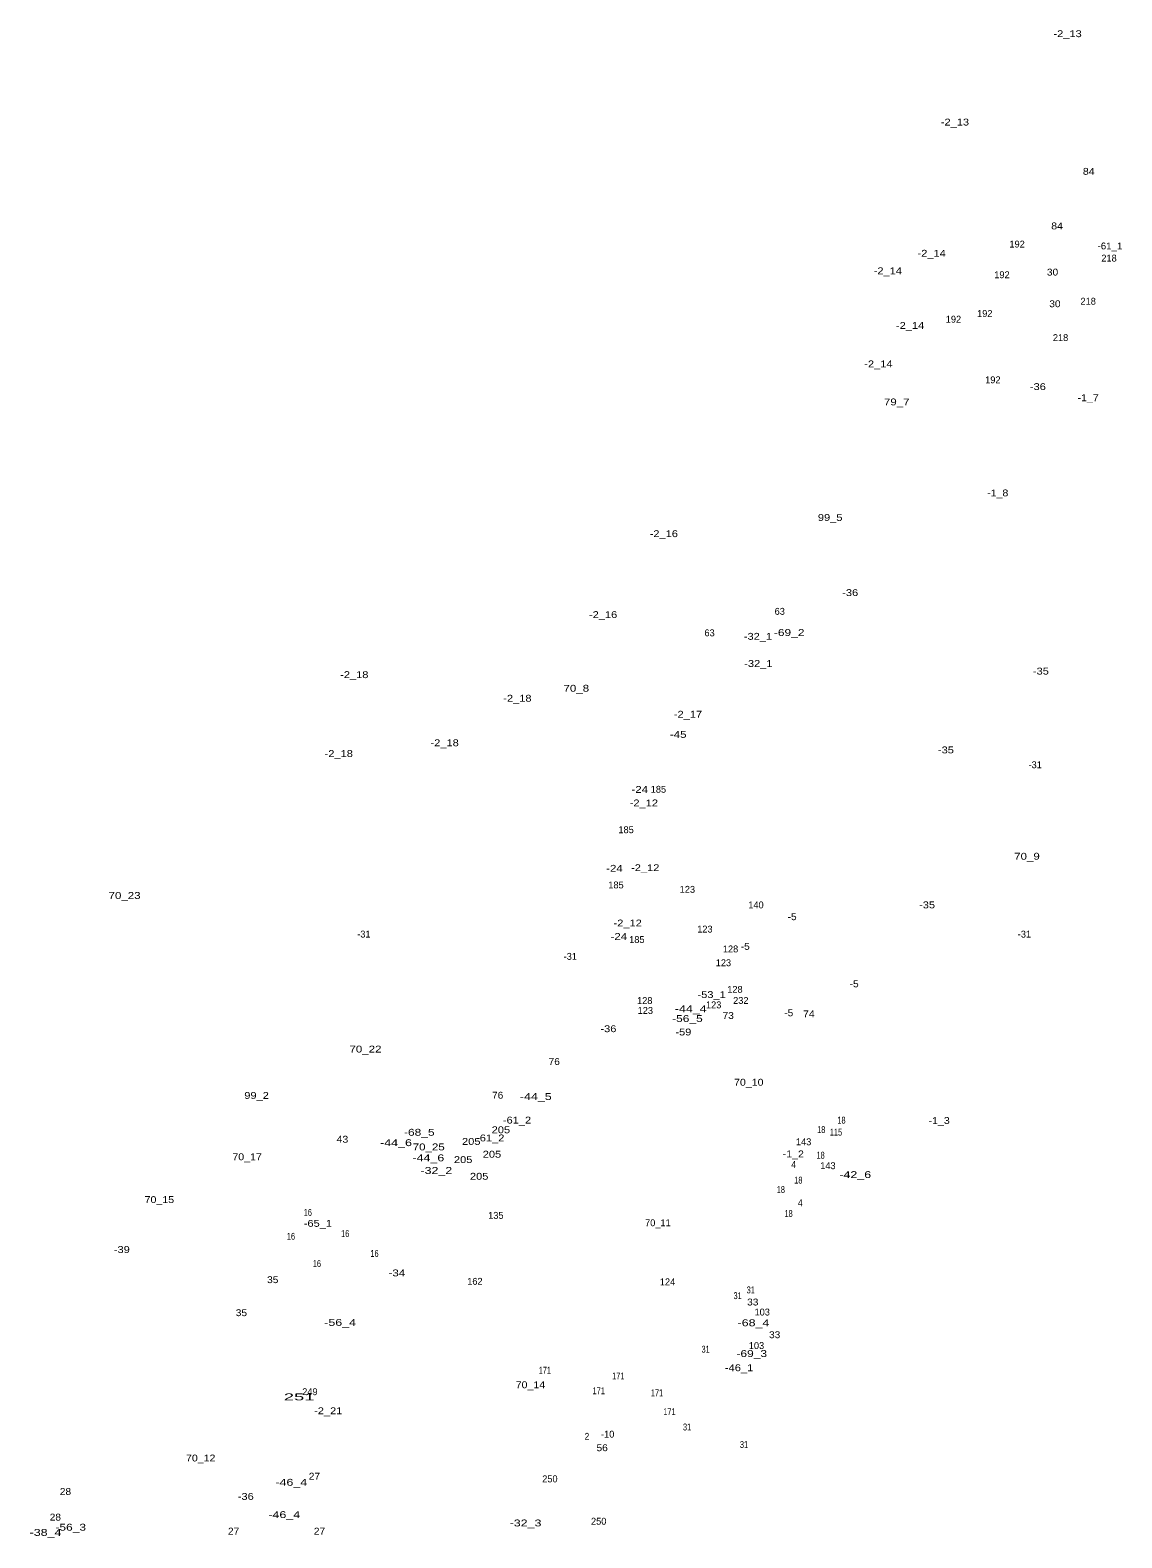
# Model space of a CAD drawing. Extents: x -659306 to -656317, y -989614 to -987663.
# Drawn here: x -658468 to -657835, y -988761 to -987886 of the extents above; entities that cross this region are included whole.
import ezdxf
from ezdxf.enums import TextEntityAlignment as Align

# ---------------------------------------------------------------- set-up
doc = ezdxf.new("R2010")
doc.units = 0
doc.header["$LTSCALE"] = 1.6
doc.layers.add('24', color=7, linetype='Continuous')

msp = doc.modelspace()

# ---------------------------------------------------------------- texts
at = {"layer": '24'}
for s, width, p in [('-2_13', 1.2, (-657866.04, -987890.05)), ('-2_13', 1.2, (-657931.429, -987941.36)), ('84', 1.15, (-657853.74, -987969.99)), ('84', 1.15, (-657872.12, -988001.68)), ('-2_14', 1.2, (-657944.939, -988017.55)), ('-61_1', 1.05, (-657841.441, -988013.3)), ('-2_14', 1.2, (-657970.39, -988027.74)), ('30', 1.1, (-657874.76, -988028.48)), ('30', 1.1, (-657873.39, -988046.86)), ('-2_14', 1.2, (-657957.47, -988059.46)), ('-2_14', 1.2, (-657975.87, -988081.79)), ('-36', 1.2, (-657883.29, -988094.98)), ('79_7', 1.25, (-657965.231, -988103.87)), ('-1_7', 1.15, (-657854.11, -988101.42)), ('-1_8', 1.15, (-657906.6, -988156.71)), ('99_5', 1.2, (-658003.87, -988170.96)), ('-2_16', 1.2, (-658100.451, -988180.36)), ('-36', 1.2, (-657992.24, -988214.59)), ('-2_16', 1.2, (-658135.691, -988227.36)), ('-69_2', 1.3, (-658027.68, -988237.76)), ('-32_1', 1.2, (-658045.799, -988239.97)), ('-32_1', 1.2, (-658045.549, -988255.73)), ('-2_18', 1.2, (-658280.16, -988262.22)), ('-35', 1.2, (-657881.53, -988260.16)), ('70_8', 1.25, (-658151.26, -988270.13)), ('-2_18', 1.2, (-658185.449, -988275.93)), ('-2_17', 1.2, (-658086.44, -988285.22)), ('-45', 1.25, (-658092.1, -988296.91)), ('-2_18', 1.2, (-658289.169, -988308.05)), ('-2_18', 1.2, (-658227.699, -988301.78)), ('-35', 1.2, (-657936.67, -988305.93)), ('-24', 1.25, (-658114.43, -988328.86)), ('-2_12', 1.2, (-658112.04, -988336.71)), ('70_9', 1.25, (-657889.6, -988367.67)), ('-24', 1.25, (-658129.11, -988374.68)), ('-2_12', 1.2, (-658111.26, -988374.31)), ('70_23', 1.25, (-658413.53, -988390.45)), ('-35', 1.2, (-657947.61, -988395.91)), ('-5', 1.1, (-658025.97, -988402.76)), ('-2_12', 1.2, (-658121.439, -988406.43)), ('-24', 1.25, (-658126.56, -988414.24)), ('-5', 1.1, (-658053.18, -988419.99)), ('-53_1', 1.2, (-658072.679, -988448)), ('-5', 1.1, (-657989.95, -988441.73)), ('-44_4', 1.35, (-658084.811, -988456.22)), ('-56_5', 1.3, (-658086.76, -988461.89)), ('73', 1.1, (-658063.05, -988460.13)), ('-5', 1.1, (-658027.92, -988458.57)), ('74', 1.15, (-658016.24, -988459.18)), ('-36', 1.2, (-658132.62, -988467.81)), ('-59', 1.2, (-658089.1, -988469.71)), ('70_22', 1.25, (-658273.669, -988479.63)), ('76', 1.1, (-658164.07, -988486.85)), ('70_10', 1.15, (-658051.12, -988498.89)), ('99_2', 1.2, (-658336.89, -988506.56)), ('76', 1.1, (-658196.92, -988506.41)), ('-44_5', 1.35, (-658174.78, -988507.18)), ('205', 1.2, (-658195.049, -988526.5)), ('-61_2', 1.2, (-658185.691, -988520.87)), ('18', 0.8, (-658009.049, -988526.37)), ('18', 0.8, (-657997.319, -988520.89)), ('-1_3', 1.15, (-657940.6, -988521.11)), ('43', 1.15, (-658287.069, -988531.99)), ('-44_6', 1.35, (-658255.929, -988533.97)), ('-68_5', 1.3, (-658242.42, -988527.95)), ('70_25', 1.25, (-658236.949, -988536.44)), ('205', 1.2, (-658212.26, -988533.25)), ('-61_2', 1.2, (-658201.231, -988531.23)), ('115', 0.8, (-658000.5, -988527.84)), ('70_17', 1.15, (-658342.39, -988542.18)), ('-44_6', 1.35, (-658237.16, -988542.78)), ('205', 1.2, (-658216.949, -988543.81)), ('205', 1.2, (-658200.23, -988540.68)), ('-1_2', 1.15, (-658025.29, -988540.51)), ('18', 0.8, (-658009.439, -988541.24)), ('-32_2', 1.35, (-658232.52, -988550.12)), ('205', 1.2, (-658207.66, -988553.5)), ('4', 0.95, (-658025.09, -988546.66)), ('-42_6', 1.35, (-657989.31, -988552.52)), ('18', 0.8, (-658032.51, -988561.19)), ('18', 0.8, (-658022.35, -988555.71)), ('70_15', 1.15, (-658393.34, -988567.03)), ('4', 0.95, (-658021.23, -988568.91)), ('16', 0.8, (-658307.15, -988574.44)), ('18', 0.8, (-658028.02, -988575.08)), ('16', 0.8, (-658316.931, -988588.33)), ('-65_1', 1.2, (-658301.291, -988580.82)), ('16', 0.8, (-658285.451, -988586.76)), ('-39', 1.2, (-658415.13, -988596.04)), ('16', 0.8, (-658301.87, -988604.17)), ('16', 0.8, (-658268.441, -988598.3)), ('35', 1.1, (-658327.51, -988613.52)), ('-34', 1.25, (-658255.45, -988609.61)), ('31', 0.8, (-658057.61, -988622.79)), ('31', 0.8, (-658049.98, -988619.46)), ('35', 1.1, (-658345.699, -988632.69)), ('33', 1.1, (-658048.809, -988626.5)), ('-56_4', 1.35, (-658288.38, -988638.36)), ('-68_4', 1.35, (-658048.4, -988638.55)), ('33', 1.1, (-658036.1, -988645.48)), ('31', 0.8, (-658076.179, -988653.89)), ('-69_3', 1.3, (-658049.4, -988656.42)), ('171', 0.8, (-658169.51, -988666.11)), ('-46_1', 1.2, (-658056.75, -988664.65)), ('70_14', 1.15, (-658177.89, -988674.55)), ('171', 0.8, (-658126.89, -988669.43)), ('251', 2, (-658312.167, -988681.58)), ('171', 0.8, (-658138.231, -988678.04)), ('171', 0.8, (-658104.4, -988679.21)), ('-2_21', 1.2, (-658295.29, -988689.65)), ('171', 0.8, (-658097.171, -988690.17)), ('31', 0.8, (-658086.939, -988699.07)), ('2', 0.9, (-658145.079, -988704.47)), ('56', 1.1, (-658136.25, -988711.1)), ('31', 0.8, (-658053.89, -988709.24)), ('70_12', 1.15, (-658369.319, -988717.08)), ('27', 1.1, (-658303.31, -988727.66)), ('28', 1.1, (-658447.85, -988736.53)), ('-46_4', 1.35, (-658316.73, -988731.18)), ('-36', 1.2, (-658343.17, -988739.38)), ('28', 1.1, (-658453.709, -988751.39)), ('-46_4', 1.35, (-658320.829, -988749.95)), ('-32_3', 1.35, (-658180.73, -988754.79)), ('-38_4', 1.35, (-658459.43, -988760.27)), ('-56_3', 1.3, (-658444.79, -988757.26)), ('27', 1.1, (-658350.23, -988759.54)), ('27', 1.1, (-658300.37, -988759.54))]:
    msp.add_text(s, height=4, dxfattribs=dict(at, width=width)).set_placement(p, align=Align.CENTER)
for s, p in [('192', (-657895.341, -988012.21)), ('218', (-657841.959, -988020.36)), ('192', (-657904.14, -988030.01)), ('218', (-657854.079, -988045.4)), ('192', (-657914.111, -988052.51)), ('192', (-657932.291, -988055.83)), ('218', (-657870.12, -988066.52)), ('192', (-657909.421, -988091.02)), ('63', (-658033.143, -988225.45)), ('63', (-658073.883, -988237.93)), ('-31', (-657884.841, -988314.55)), ('185', (-658103.59, -988328.79)), ('185', (-658122.36, -988352.26)), ('185', (-658128.23, -988384.34)), ('123', (-658086.77, -988386.87)), ('140', (-658046.939, -988395.91)), ('-31', (-658274.571, -988412.86)), ('123', (-658076.61, -988409.95)), ('-31', (-657891.101, -988412.86)), ('185', (-658116.1, -988416.03)), ('128', (-658061.709, -988421.49)), ('-31', (-658154.76, -988425.79)), ('123', (-658065.85, -988429.51)), ('128', (-658059.169, -988444.96)), ('128', (-658111.53, -988451.46)), ('123', (-658111.199, -988457.2)), ('123', (-658071.52, -988453.96)), ('232', (-658055.747, -988451.39)), ('143', (-658019.28, -988533.45)), ('143', (-658005.199, -988547.34)), ('135', (-658197.97, -988576.18)), ('70_11', (-658103.89, -988580.48)), ('162', (-658210.15, -988614.48)), ('124', (-658098.309, -988614.78)), ('103', (-658043.33, -988632.32)), ('103', (-658046.65, -988651.78)), ('249', (-658305.927, -988678.57)), ('-10', (-658133.03, -988703.23)), ('250', (-658166.591, -988729.17)), ('250', (-658138.251, -988753.78))]:
    msp.add_text(s, height=4, dxfattribs=at).set_placement(p, align=Align.CENTER)

doc.saveas('drawing.dxf')
